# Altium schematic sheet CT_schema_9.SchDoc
size 274 x 160 mm
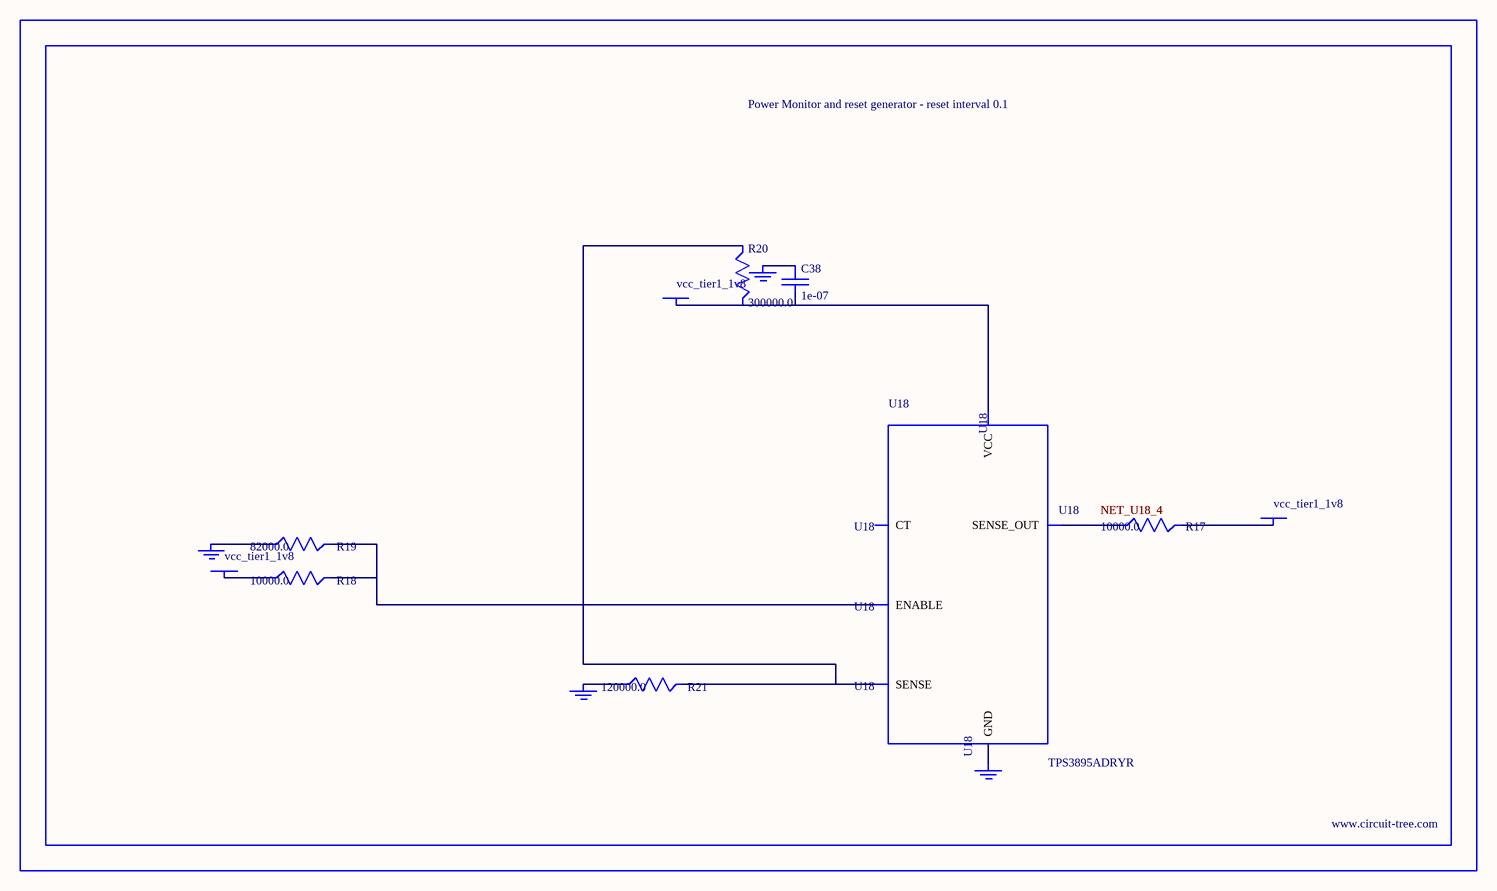
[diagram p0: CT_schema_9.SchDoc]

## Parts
BORDER8  (no value)
C38  1e-07  [C0402]
GND_INSTANCE_8_0  (no value)
GND_INSTANCE_8_1  (no value)
GND_INSTANCE_8_2  (no value)
GND_INSTANCE_8_3  (no value)
POWER_INSTANCE_8_0  vcc_tier1_1v8
POWER_INSTANCE_8_1  vcc_tier1_1v8
POWER_INSTANCE_8_2  vcc_tier1_1v8
R17  10000.0  [R0603]
R18  10000.0  [R0603]
R19  82000.0  [R0603]
R20  300000.0  [R0603]
R21  120000.0  [R0603]
U18  TPS3895ADRYR  [SON-6]

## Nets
NetC38_1: C38.1 GND_INSTANCE_8_2.0(GND)
NetC38_2: C38.2 POWER_INSTANCE_8_2.0(PWR) R20.2 U18.6(VCC)
NetGND_INSTANCE_8_0_0: GND_INSTANCE_8_0.0(GND) R19.1
NetGND_INSTANCE_8_1_0: GND_INSTANCE_8_1.0(GND) R21.1
NetGND_INSTANCE_8_3_0: GND_INSTANCE_8_3.0(GND) U18.2(GND)
NetPOWER_INSTANCE_8_0_0: POWER_INSTANCE_8_0.0(PWR) R18.1
NetPOWER_INSTANCE_8_1_0: POWER_INSTANCE_8_1.0(PWR) R17.2
NetR17_1: R17.1 U18.4(SENSE_OUT)
NetR18_2: R18.2 R19.2 U18.1(ENABLE)
NetR20_1: R20.1 R21.2 U18.3(SENSE)

Not connected (* = marked no-connect by the designer): U18 5(CT)

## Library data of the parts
BORDER8 = BORDER_PAGE8
C38 = C0402C104K3RACTU
GND_INSTANCE_8_0-GND_INSTANCE_8_3 = GND
POWER_INSTANCE_8_0-POWER_INSTANCE_8_2 = PWR
R17 R18 = RC0603JR-0710KL
R19 = RC0603JR-0782KL
R20 = RC0603JR-07300KL
R21 = RC0603JR-07120KL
